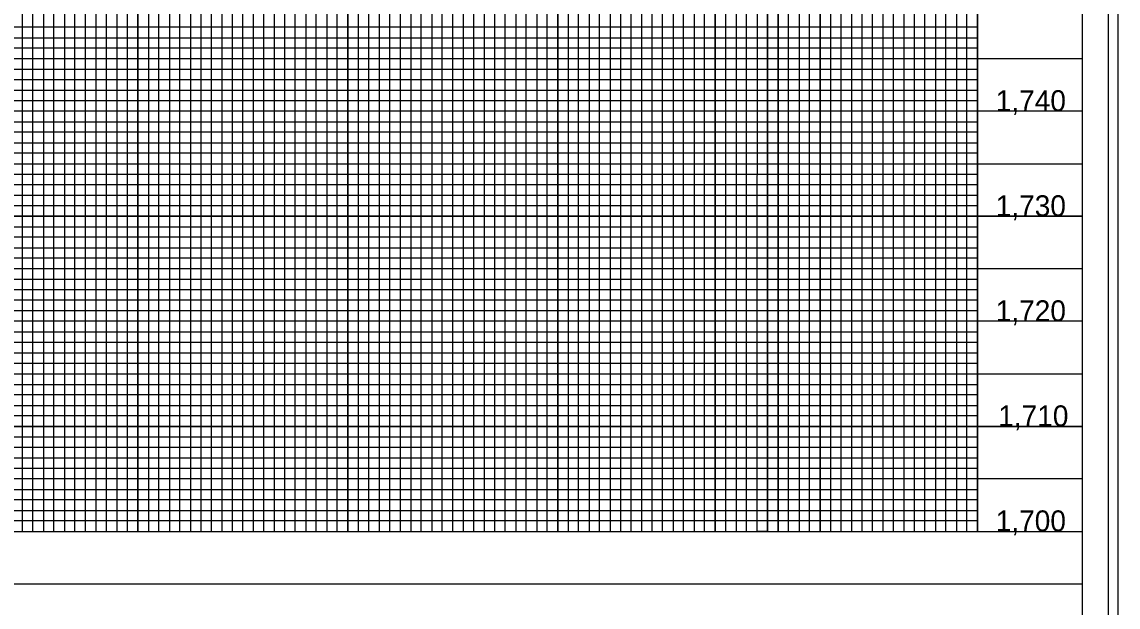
# Model space of a CAD drawing. Extents: x 505237 to 506921, y 424821 to 425921.
# Drawn here: x 506398 to 506921, y 425360 to 425638 of the extents above; entities that cross this region are included whole.
import ezdxf

# ---------------------------------------------------------------- set-up
doc = ezdxf.new("R2010")
doc.units = 0
for name, color, linetype in [('Exist Vertical Profile Vertical Axis Label', 7, 'Continuous'), ('Matchline', 7, 'Continuous'), ('Prop Horizontal Alignment Station Label', 7, 'Continuous'), ('Sheet Cutting Line CELL', 7, 'Continuous'), ('Sheet DOT Grid CELL', 7, 'Continuous'), ('Sheet Plot Border Inside CELL', 7, 'Continuous'), ('Sheet Plot Border Outside CELL', 7, 'Continuous'), ('Sheet Sticker Incomplete CELL', 7, 'Continuous')]:
    doc.layers.add(name, color=color, linetype=linetype)

msp = doc.modelspace()

# ---------------------------------------------------------------- linework, layer by layer
at = {"layer": 'Matchline'}
for points in [[(506378.71, 425395.67), (506428.71, 425395.67), (506428.71, 425895.67), (506478.71, 425895.67), (506478.71, 425395.67), (506528.71, 425395.67), (506528.71, 425895.67), (506578.71, 425895.67), (506578.71, 425395.67), (506628.71, 425395.67), (506628.71, 425895.67), (506678.71, 425895.67), (506678.71, 425395.67), (506728.71, 425395.67), (506728.71, 425734.62)], [(506728.71, 425658.47), (506728.71, 425395.67), (506778.71, 425395.67), (506778.71, 425734.62)], [(506778.71, 425658.47), (506778.71, 425395.67), (506828.71, 425395.67), (506828.71, 425734.62)], [(506903.71, 425620.67), (505403.71, 425620.67), (505403.71, 425570.67), (506903.71, 425570.67)], [(506903.71, 425520.67), (505403.71, 425520.67), (505403.71, 425470.67), (506903.71, 425470.67)], [(506903.71, 425420.67), (505403.71, 425420.67)]]:
    msp.add_lwpolyline(points, dxfattribs=at)
at = {"layer": 'Prop Horizontal Alignment Station Label'}
for p, q in [((505403.71, 425395.67), (506903.71, 425395.67)), ((505403.71, 425370.67), (506903.71, 425370.67))]:
    msp.add_line(p, q, dxfattribs=at)
msp.add_lwpolyline([(506903.71, 425895.67), (505403.71, 425895.67), (505403.71, 424845.67), (506903.71, 424845.67)], close=True, dxfattribs=at)
at = {"layer": 'Sheet Cutting Line CELL'}
for p, q in [((506403.71, 425370.67), (506453.71, 425370.67)), ((506503.71, 425370.67), (506553.71, 425370.67)), ((506603.71, 425370.67), (506653.71, 425370.67)), ((506703.71, 425370.67), (506753.71, 425370.67)), ((506803.71, 425370.67), (506853.71, 425370.67))]:
    msp.add_line(p, q, dxfattribs=at)
for points in [[(506353.71, 425395.67), (506403.71, 425395.67), (506403.71, 425895.67), (506453.71, 425895.67), (506453.71, 425395.67), (506503.71, 425395.67), (506503.71, 425895.67), (506553.71, 425895.67), (506553.71, 425395.67), (506603.71, 425395.67), (506603.71, 425895.67), (506653.71, 425895.67), (506653.71, 425395.67), (506703.71, 425395.67), (506703.71, 425895.67), (506730.01, 425895.67)], [(506853.71, 425734.62), (506853.71, 425395.67), (506903.71, 425395.67), (506903.71, 425745.67)], [(506753.71, 425734.62), (506753.71, 425395.67), (506803.71, 425395.67), (506803.71, 425395.67), (506803.71, 425734.62)], [(506903.71, 425595.67), (505403.71, 425595.67), (505403.71, 425545.67), (506903.71, 425545.67)], [(506903.71, 425495.67), (505403.71, 425495.67), (505403.71, 425495.67), (505403.71, 425445.67), (506903.71, 425445.67)]]:
    msp.add_lwpolyline(points, dxfattribs=at)
at = {"layer": 'Sheet DOT Grid CELL'}
for p, q in [((506403.71, 425395.67), (506403.71, 425895.67)), ((506453.71, 425395.67), (506453.71, 425895.67)), ((506503.71, 425395.67), (506503.71, 425895.67)), ((506553.71, 425395.67), (506553.71, 425895.67)), ((506603.71, 425395.67), (506603.71, 425895.67)), ((506653.71, 425395.67), (506653.71, 425895.67)), ((506703.71, 425395.67), (506703.71, 425758.12)), ((506753.71, 425395.67), (506753.71, 425734.62)), ((506803.71, 425395.67), (506803.71, 425734.62)), ((506853.71, 425395.67), (506853.71, 425734.62)), ((506903.71, 425595.67), (505403.71, 425595.67)), ((506903.71, 425545.67), (505403.71, 425545.67)), ((506903.71, 425495.67), (505403.71, 425495.67)), ((506903.71, 425445.67), (505403.71, 425445.67)), ((505403.71, 425370.67), (506903.6, 425370.67))]:
    msp.add_line(p, q, dxfattribs=at)
at = {"layer": 'Sheet Plot Border Inside CELL'}
msp.add_lwpolyline([(505249.71, 424843.12), (506916.21, 424843.12), (506916.21, 425898.22), (505249.71, 425898.22)], close=True, dxfattribs=at)
at = {"layer": 'Sheet Plot Border Outside CELL'}
msp.add_lwpolyline([(505236.71, 424820.67), (506920.71, 424820.67), (506920.71, 425920.67), (505236.71, 425920.67)], close=True, dxfattribs=at)
at = {"layer": 'Sheet Sticker Incomplete CELL'}
for p, q in [((506853.71, 425635.67), (505453.71, 425635.67)), ((505453.71, 425630.67), (506853.71, 425630.67)), ((506853.71, 425625.67), (505453.71, 425625.67)), ((505453.71, 425615.67), (506853.71, 425615.67)), ((506853.71, 425610.67), (505453.71, 425610.67)), ((505453.71, 425605.67), (506853.71, 425605.67)), ((506853.71, 425600.67), (505453.71, 425600.67)), ((505453.71, 425590.67), (506853.71, 425590.67)), ((506853.71, 425585.67), (505453.71, 425585.67)), ((505453.71, 425580.67), (506853.71, 425580.67)), ((506853.71, 425575.67), (505453.71, 425575.67)), ((505453.71, 425565.67), (506853.71, 425565.67)), ((506853.71, 425560.67), (505453.71, 425560.67)), ((505453.71, 425555.67), (506853.71, 425555.67)), ((506853.71, 425550.67), (505453.71, 425550.67)), ((505453.71, 425540.67), (506853.71, 425540.67)), ((506853.71, 425535.67), (505453.71, 425535.67)), ((505453.71, 425530.67), (506853.71, 425530.67)), ((506853.71, 425525.67), (505453.71, 425525.67)), ((505453.71, 425515.67), (506853.71, 425515.67)), ((506853.71, 425510.67), (505453.71, 425510.67)), ((506853.71, 425505.67), (505453.71, 425505.67)), ((506853.71, 425500.67), (505453.71, 425500.67)), ((505453.71, 425490.67), (506853.71, 425490.67)), ((506853.71, 425485.67), (505453.71, 425485.67)), ((505453.71, 425480.67), (506853.71, 425480.67)), ((506853.71, 425475.67), (505453.71, 425475.67)), ((505453.71, 425465.67), (506853.71, 425465.67)), ((506853.71, 425460.67), (505453.71, 425460.67)), ((505453.71, 425455.67), (506853.71, 425455.67)), ((506853.71, 425450.67), (505453.71, 425450.67)), ((505453.71, 425440.67), (506853.71, 425440.67)), ((506853.71, 425435.67), (505453.71, 425435.67)), ((505453.71, 425430.67), (506853.71, 425430.67)), ((506853.71, 425425.67), (505453.71, 425425.67)), ((505453.71, 425415.67), (506853.71, 425415.67)), ((506853.71, 425410.67), (505453.71, 425410.67)), ((505453.71, 425405.67), (506853.71, 425405.67))]:
    msp.add_line(p, q, dxfattribs=at)
for points in [[(506393.71, 425395.67), (506398.71, 425395.67), (506398.71, 425895.67)], [(506408.71, 425895.67), (506408.71, 425395.67), (506413.71, 425395.67), (506413.71, 425895.67)], [(506418.71, 425895.67), (506418.71, 425395.67), (506423.71, 425395.67), (506423.71, 425895.67)], [(506433.71, 425895.67), (506433.71, 425395.67), (506438.71, 425395.67), (506438.71, 425895.67)], [(506443.71, 425895.67), (506443.71, 425395.67), (506448.71, 425395.67), (506448.71, 425895.67)], [(506458.71, 425895.67), (506458.71, 425395.67), (506463.71, 425395.67), (506463.71, 425895.67)], [(506468.71, 425895.67), (506468.71, 425395.67), (506473.71, 425395.67), (506473.71, 425895.67)], [(506483.71, 425895.67), (506483.71, 425395.67), (506488.71, 425395.67), (506488.71, 425895.67)], [(506493.71, 425895.67), (506493.71, 425395.67), (506498.71, 425395.67), (506498.71, 425895.67)], [(506508.71, 425895.67), (506508.71, 425395.67), (506513.71, 425395.67), (506513.71, 425895.67)], [(506518.71, 425895.67), (506518.71, 425395.67), (506523.71, 425395.67), (506523.71, 425895.67)], [(506533.71, 425895.67), (506533.71, 425395.67), (506538.71, 425395.67), (506538.71, 425895.67)], [(506543.71, 425895.67), (506543.71, 425395.67), (506548.71, 425395.67), (506548.71, 425895.67)], [(506558.71, 425895.67), (506558.71, 425395.67), (506563.71, 425395.67), (506563.71, 425895.67)], [(506568.71, 425895.67), (506568.71, 425395.67), (506573.71, 425395.67), (506573.71, 425895.67)], [(506583.71, 425895.67), (506583.71, 425395.67), (506588.71, 425395.67), (506588.71, 425895.67)], [(506593.71, 425895.67), (506593.71, 425395.67)], [(506593.71, 425395.67), (506598.71, 425395.67), (506598.71, 425895.67)], [(506608.71, 425895.67), (506608.71, 425395.67), (506613.71, 425395.67), (506613.71, 425895.67)], [(506618.71, 425895.67), (506618.71, 425395.67), (506623.71, 425395.67), (506623.71, 425895.67)], [(506633.71, 425895.67), (506633.71, 425395.67), (506638.71, 425395.67), (506638.71, 425895.67)], [(506643.71, 425895.67), (506643.71, 425395.67), (506648.71, 425395.67), (506648.71, 425895.67)], [(506658.71, 425895.67), (506658.71, 425395.67), (506663.71, 425395.67), (506663.71, 425895.67)], [(506668.71, 425895.67), (506668.71, 425395.67), (506673.71, 425395.67), (506673.71, 425895.67)], [(506683.71, 425895.67), (506683.71, 425395.67), (506688.71, 425395.67), (506688.71, 425895.67)], [(506693.71, 425895.67), (506693.71, 425395.67), (506698.71, 425395.67), (506698.71, 425895.67)], [(506708.71, 425734.62), (506708.71, 425395.67), (506713.71, 425395.67), (506713.71, 425734.62)], [(506718.71, 425734.62), (506718.71, 425395.67), (506723.71, 425395.67), (506723.71, 425734.62)], [(506733.71, 425734.62), (506733.71, 425395.67), (506733.71, 425395.67), (506738.71, 425395.67), (506743.71, 425395.67), (506743.71, 425734.62)], [(506738.71, 425734.62), (506738.71, 425395.67)], [(506748.71, 425734.62), (506748.61, 425395.72), (506753.61, 425395.72), (506758.71, 425395.67), (506758.71, 425734.62)], [(506758.71, 425658.47), (506758.71, 425395.67), (506763.71, 425395.67), (506763.71, 425734.62)], [(506768.71, 425734.62), (506768.71, 425395.67), (506773.71, 425395.67), (506773.71, 425734.62)], [(506783.71, 425734.62), (506783.71, 425395.67), (506788.71, 425395.67), (506788.71, 425734.62)], [(506793.71, 425734.62), (506793.71, 425395.67), (506798.71, 425395.67), (506798.71, 425734.62)], [(506808.71, 425734.62), (506808.71, 425395.67), (506813.71, 425395.67), (506813.71, 425734.62)], [(506818.71, 425734.62), (506818.71, 425395.67), (506823.71, 425395.67), (506823.71, 425734.62)], [(506833.71, 425734.62), (506833.71, 425395.67), (506838.71, 425395.67), (506838.71, 425734.62)], [(506843.71, 425734.62), (506843.71, 425395.67), (506848.71, 425395.67), (506848.71, 425734.62)], [(506853.71, 425400.67), (505453.71, 425400.67)]]:
    msp.add_lwpolyline(points, dxfattribs=at)

# ---------------------------------------------------------------- texts
at = {"layer": 'Exist Vertical Profile Vertical Axis Label'}
for s, p in [('1,740', (506862.41, 425595.67)), ('1,730', (506862.41, 425545.67)), ('1,720', (506862.41, 425495.67)), ('1,710', (506863.61, 425445.67)), ('1,700', (506862.41, 425395.67))]:
    msp.add_text(s, height=10, dxfattribs=at).set_placement(p)

doc.saveas('drawing.dxf')
